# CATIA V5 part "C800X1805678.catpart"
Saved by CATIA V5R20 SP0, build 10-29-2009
Part number: C800X1805678
Source: Unknown
Property "A": "70"
Property "ARTICLENO": "C800X1805678"
Property "B": "32"
Property "BOMINFO": "C800X1805678"
Property "C": "120"
Property "CA": "C800X1805678"
Property "D1": "120"
Property "DES": "ROTATING EYEBOLT WITH RING Ton 18,0 M56x78"
Property "E": "112"
Property "H": "262"
Property "L": "78"
Property "LINA": "C800X1805678"
Property "NB": "C800X1805678"
Property "NBSYN": "$CODE."
Property "NN": "C800X"
Property "NT": "Rotating eyebolt with ring"
Property "SIZE": "M56"
Property "SUPPLIER": "CF"
Property "SW": "100"
Property "WEIGHT": "10900"
Property "WLL": "18.00"
Bounding box of the stored display mesh (mm): x -67 to 67, y -78 to 293.813, z -60 to 60
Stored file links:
  C:\Users\Utente\Desktop\3D files 800X\C800X1805678.catpart
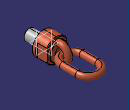
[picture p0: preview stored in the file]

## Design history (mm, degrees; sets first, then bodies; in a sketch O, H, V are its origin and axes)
Body1 "Geometry.1" (main body)
  Solid1 "C800X1805678.catpart": solid without history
